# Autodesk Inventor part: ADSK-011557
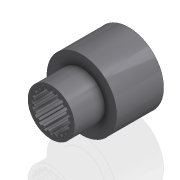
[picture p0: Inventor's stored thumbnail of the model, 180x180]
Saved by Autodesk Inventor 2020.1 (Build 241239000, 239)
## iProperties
Created: 2000-01
Part Number: ADSK-011557
Material: Acier doux
Document SubType Name: Modeling
Designer: tgregory
Density: 7.86 g/cm^3
Appearance: Metal-Steel(Polish)
Mass: 620.354 g
Surface Area: 235.474 cm^2
Volume: 78.9255 cm^3
Control State: 0
Master: False
Checked Out: False
Shininess: 0.0
Length Units: 11269
Angle Units: 11279
Time Units: 11290
Mass Units: 11283
Length Display Precision: 3
Angle Display Precision: 2
Compacted: True
Dimensions: 57x63,5x57 mm
Mass: 0,62 kg
VLT_Material: Acier doux
Density: 0.0
Volumn: 0.0
Area: 0.0
PropertySet Name: Model Information
Author: tgregory
Revision Number: -
Title: ADSK-011557
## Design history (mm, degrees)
node "Solide1"
  node "Extrusion1" dims "d8" = 25, "d9" = 0
  node "Extrusion2" dims "d14" = 63.5, "d15" = 0
  node "Extrusion3" dims "d16" = 50.8, "d17" = 0
  node "Extrusion4" dims "d19" = 25, "d20" = 0
  node "Hole1" dims "d22" = 8.376, "d23" = 9.525, "d24" = 6.35, "d25" = 60 deg, "d26" = 27.3, "d27" = 118 deg, "d35" = 20
  node "Hole2" dims "d28" = 8.376, "d29" = 9.525, "d30" = 6.35, "d31" = 60 deg, "d32" = 27.3, "d33" = 118 deg, "d36" = 20
sketch "Sketch1"
  geometry: L1 (0, 16)-(0, 0) reference; L2 (1.4, 14.181)-(1.15, 15.959); L3 (-1.15, 15.959)-(-1.4, 14.181); A1 r 14.25 centre (0, 0) between (1.4, 14.181) and (-1.4, 14.181); A2 r 16 centre (0, 0) between (1.15, 15.959) and (-1.15, 15.959); 1 further point
  constraints: 6 end point, 5 point on circle, 3 coincident, 2 centre point, 1 vertical
  dimensions: "d0" = 28.5 diameter of A1; "d1" = 32 diameter of A2; "d4" = 1.15 distance from line of L2.end L1; "d5" = 1.4 distance from line of L2.start L1; "d6" = 1.15 distance from line of L3.start L1 (= d4); "d7" = 1.4 distance from line of L3.end L1 (= d5)
sketch "Sketch3"
  geometry: L1 (-28.5, 0)-(28.5, 0) reference; L2 (-28.5, 0)-(28.5, 0); L3 (28.5, 0)-(28.5, -25); L4 (28.5, -25)-(-28.5, -25); L5 (-28.5, -25)-(-28.5, 0); L6 (-15.959, -25)-(-16, -25) reference; 2 further points
  constraints: 8 end point, 2 perpendicular, 1 horizontal, 1 midpoint, 1 parallel, 1 point on line, 1 other
sketch "Sketch4"
  geometry: C1 r 28.5 at (0, 0) reference; C2 r 19 at (0, 0)
  constraints: 1 centre point, 1 coincident
  dimensions: "d18" = 38 diameter of C2
workplane "Work Plane1"
workaxis "Work Axis2"
workaxis "Work Axis3"
workplane "Work Plane2"
workaxis "Work Axis4"
workaxis "Work Axis1"
sketch "Sketch2"
  geometry: L1 (-5.714, -13.054)-(-6.025, -14.822) reference; L2 (-3.838, -15.533)-(-3.051, -13.92) reference; L3 (-1.4, -14.181)-(-1.15, -15.959) reference; L4 (1.15, -15.959)-(1.4, -14.181) reference; L5 (3.051, -13.92)-(3.838, -15.533) reference; L6 (6.025, -14.822)-(5.714, -13.054) reference; L7 (7.203, -12.296)-(8.45, -13.587) reference; L8 (10.311, -12.235)-(9.468, -10.65) reference; L9 (10.65, -9.468)-(12.235, -10.311) reference; L10 (13.587, -8.45)-(12.296, -7.203) reference; L11 (13.054, -5.714)-(14.822, -6.025) reference; L12 (15.533, -3.838)-(13.92, -3.051) reference; L13 (14.181, -1.4)-(15.959, -1.15) reference; L14 (15.959, 1.15)-(14.181, 1.4) reference; L15 (13.92, 3.051)-(15.533, 3.838) reference; L16 (14.822, 6.025)-(13.054, 5.714) reference; L17 (12.296, 7.203)-(13.587, 8.45) reference; L18 (12.235, 10.311)-(10.65, 9.468) reference; L19 (9.468, 10.65)-(10.311, 12.235) reference; L20 (8.45, 13.587)-(7.203, 12.296) reference; L21 (5.714, 13.054)-(6.025, 14.822) reference; L22 (3.838, 15.533)-(3.051, 13.92) reference; L23 (1.4, 14.181)-(1.15, 15.959) reference; L24 (-1.15, 15.959)-(-1.4, 14.181) reference; L25 (-3.051, 13.92)-(-3.838, 15.533) reference; L26 (-6.025, 14.822)-(-5.714, 13.054) reference; L27 (-7.203, 12.296)-(-8.45, 13.587) reference; L28 (-10.311, 12.235)-(-9.468, 10.65) reference; L29 (-10.65, 9.468)-(-12.235, 10.311) reference; L30 (-13.587, 8.45)-(-12.296, 7.203) reference; L31 (-13.054, 5.714)-(-14.822, 6.025) reference; L32 (-15.533, 3.838)-(-13.92, 3.051) reference; L33 (-14.181, 1.4)-(-15.959, 1.15) reference; L34 (-15.959, -1.15)-(-14.181, -1.4) reference; L35 (-13.92, -3.051)-(-15.533, -3.838) reference; L36 (-14.822, -6.025)-(-13.054, -5.714) reference; L37 (-12.296, -7.203)-(-13.587, -8.45) reference; L38 (-12.235, -10.311)-(-10.65, -9.468) reference; L39 (-9.468, -10.65)-(-10.311, -12.235) reference; L40 (-8.45, -13.587)-(-7.203, -12.296) reference; C1 r 28.5 at (0, 0); A1 r 16 centre (0, 0) between (-6.025, -14.822) and (-3.838, -15.533) reference; A2 r 14.25 centre (0, 0) between (-3.051, -13.92) and (-1.4, -14.181) reference; A3 r 16 centre (0, 0) between (-1.15, -15.959) and (1.15, -15.959) reference; A4 r 14.25 centre (0, 0) between (1.4, -14.181) and (3.051, -13.92) reference; A5 r 16 centre (0, 0) between (3.838, -15.533) and (6.025, -14.822) reference; A6 r 14.25 centre (0, 0) between (5.714, -13.054) and (7.203, -12.296) reference; A7 r 16 centre (0, 0) between (8.45, -13.587) and (10.311, -12.235) reference; A8 r 14.25 centre (0, 0) between (9.468, -10.65) and (10.65, -9.468) reference; A9 r 16 centre (0, 0) between (12.235, -10.311) and (13.587, -8.45) reference; A10 r 14.25 centre (0, 0) between (12.296, -7.203) and (13.054, -5.714) reference; A11 r 16 centre (0, 0) between (14.822, -6.025) and (15.533, -3.838) reference; A12 r 14.25 centre (0, 0) between (13.92, -3.051) and (14.181, -1.4) reference; A13 r 16 centre (0, 0) between (15.959, -1.15) and (15.959, 1.15) reference; A14 r 14.25 centre (0, 0) between (14.181, 1.4) and (13.92, 3.051) reference; A15 r 16 centre (0, 0) between (15.533, 3.838) and (14.822, 6.025) reference; A16 r 14.25 centre (0, 0) between (13.054, 5.714) and (12.296, 7.203) reference; A17 r 16 centre (0, 0) between (13.587, 8.45) and (12.235, 10.311) reference; A18 r 14.25 centre (0, 0) between (10.65, 9.468) and (9.468, 10.65) reference; A19 r 16 centre (0, 0) between (10.311, 12.235) and (8.45, 13.587) reference; A20 r 14.25 centre (0, 0) between (7.203, 12.296) and (5.714, 13.054) reference; A21 r 16 centre (0, 0) between (6.025, 14.822) and (3.838, 15.533) reference; A22 r 14.25 centre (0, 0) between (3.051, 13.92) and (1.4, 14.181) reference; A23 r 16 centre (0, 0) between (1.15, 15.959) and (-1.15, 15.959) reference; A24 r 14.25 centre (0, 0) between (-1.4, 14.181) and (-3.051, 13.92) reference; A25 r 16 centre (0, 0) between (-3.838, 15.533) and (-6.025, 14.822) reference; A26 r 14.25 centre (0, 0) between (-5.714, 13.054) and (-7.203, 12.296) reference; A27 r 16 centre (0, 0) between (-8.45, 13.587) and (-10.311, 12.235) reference; A28 r 14.25 centre (0, 0) between (-9.468, 10.65) and (-10.65, 9.468) reference; A29 r 16 centre (0, 0) between (-12.235, 10.311) and (-13.587, 8.45) reference; A30 r 14.25 centre (0, 0) between (-12.296, 7.203) and (-13.054, 5.714) reference; A31 r 16 centre (0, 0) between (-14.822, 6.025) and (-15.533, 3.838) reference; A32 r 14.25 centre (0, 0) between (-13.92, 3.051) and (-14.181, 1.4) reference; A33 r 16 centre (0, 0) between (-15.959, 1.15) and (-15.959, -1.15) reference; A34 r 14.25 centre (0, 0) between (-14.181, -1.4) and (-13.92, -3.051) reference; A35 r 16 centre (0, 0) between (-15.533, -3.838) and (-14.822, -6.025) reference; A36 r 14.25 centre (0, 0) between (-13.054, -5.714) and (-12.296, -7.203) reference; A37 r 16 centre (0, 0) between (-13.587, -8.45) and (-12.235, -10.311) reference; A38 r 14.25 centre (0, 0) between (-10.65, -9.468) and (-9.468, -10.65) reference; A39 r 16 centre (0, 0) between (-10.311, -12.235) and (-8.45, -13.587) reference; A40 r 14.25 centre (0, 0) between (-7.203, -12.296) and (-5.714, -13.054) reference
  constraints: 1 centre point, 1 coincident
  dimensions: "d13" = 57 diameter of C1
node "Corps solides"
node "Corps surfaciques"
node "Circular Pattern1" dims "d10" = 200, "d12" = 360 deg
sketch "Sketch5"
  geometry: 2 further points
  constraints: 1 coincident
sketch "Sketch6"
  geometry: 2 further points
  constraints: 1 coincident
other parameters: "d21" = -19.05, "d34" = -41.275
